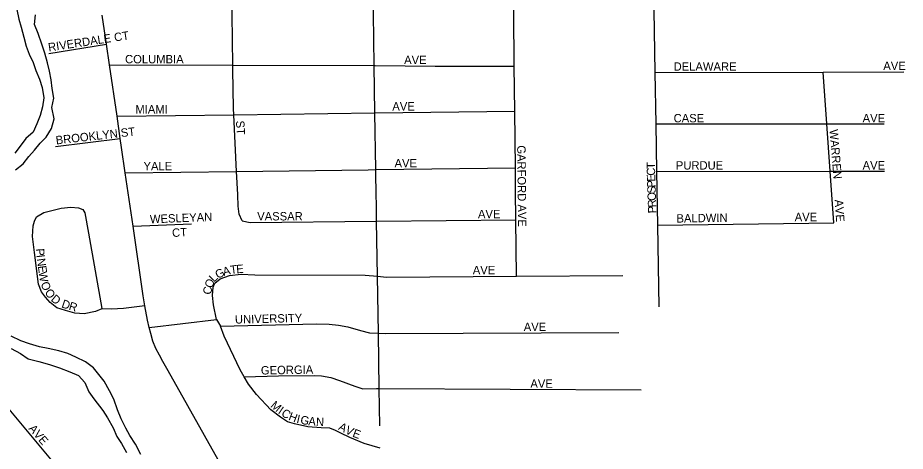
# Model space of a CAD drawing. Extents: x 1857828 to 2277390, y 930619 to 1324581.
# Drawn here: x 2077646 to 2082935, y 1221472 to 1224059 of the extents above; entities that cross this region are included whole.
import ezdxf

# ---------------------------------------------------------------- set-up
doc = ezdxf.new("R2010")
doc.units = 0
for name, color, linetype in [('GM_X_City_Street', 7, 'Continuous'), ('GM_X_City_Street_Text', 7, 'Continuous'), ('GM_X_Major_River', 7, 'Continuous')]:
    doc.layers.add(name, color=color, linetype=linetype)

msp = doc.modelspace()

# ---------------------------------------------------------------- linework, layer by layer
at = {"layer": 'GM_X_City_Street'}
for points in [[(2079782.7, 1222985.2), (2079780.2, 1223153), (2079775, 1223490.8), (2079770.7, 1223773.6), (2079765.9, 1224084.8), (2079761.3, 1224391.1), (2079756.6, 1224694.9), (2079751.2, 1225048), (2079745.7, 1225408.2), (2079740.6, 1225747.7), (2079735.5, 1226074.6), (2079730.8, 1226385.8), (2079726.5, 1226666.8), (2079721.1, 1227020.2)], [(2080613.1, 1223041.7), (2080611.7, 1223164.2), (2080608, 1223501.1), (2080605.1, 1223769.8), (2080601.6, 1224090.5), (2080598.3, 1224399.4), (2080594.9, 1224706.3), (2080591, 1225061.2), (2080587.1, 1225424.1), (2080583.5, 1225757), (2080580, 1226078.3), (2080576.5, 1226394.5), (2080573.5, 1226674.3), (2080570, 1226994.3)], [(2081468.2, 1222334), (2081460.3, 1222821.1), (2081455.1, 1223142), (2081450.5, 1223426.8), (2081445.5, 1223731.6), (2081439.4, 1224104.6), (2081434.5, 1224409.2), (2081429.3, 1224730.2), (2081423.8, 1225071.1), (2081418.2, 1225412), (2081412.5, 1225767), (2081407.3, 1226084), (2081402.1, 1226402.9), (2081397.6, 1226681.5), (2081397.4, 1226692.4)], [(2078928.2, 1223749.3), (2078928.1, 1223751.5), (2078927.8, 1223776.3), (2078923.7, 1224079.1), (2078919.5, 1224382.8), (2078915.5, 1224683.5), (2078915.1, 1224709.9)], [(2078009.5, 1221179), (2078009.1, 1221179.8), (2077998, 1221198.3), (2077931.3, 1221300.2), (2077896.6, 1221356.3), (2077842.5, 1221426.1), (2077284.2, 1222092.8), (2077253.9, 1222126.7), (2077239.8, 1222144.7), (2077229.8, 1222158.7), (2077219.6, 1222186.7), (2077213.2, 1222252.9), (2077202.8, 1222517.1), (2077194.6, 1222724.3), (2077192.6, 1222781), (2077192.3, 1222788.5), (2077197.8, 1222882.9), (2077199.4, 1223069.7), (2077201.8, 1223354.4), (2077204.6, 1223695.4), (2077205.8, 1223837.7), (2077206.6, 1223930), (2077208.3, 1224140.5)], [(2078886.5, 1221340.6), (2078876.9, 1221357.6), (2078542.6, 1221952.2), (2078510.2, 1222008.2), (2078490, 1222046.1), (2078469.8, 1222086.2), (2078451.5, 1222130.2), (2078439.2, 1222174.3), (2078429.8, 1222211.3), (2078418.8, 1222254.4), (2078404.2, 1222340.3), (2078393.9, 1222400.7), (2078333.6, 1222814.5), (2078287.1, 1223132.9), (2078265, 1223284.9), (2078257.1, 1223338.6), (2078237.5, 1223471.8), (2078192.3, 1223778.7), (2078174.2, 1223901.7), (2078148.9, 1224073.8)], [(2077830.5, 1223844.9), (2078174.2, 1223901.7)], [(2078192.3, 1223778.7), (2078927.8, 1223776.3), (2079770.7, 1223773.6), (2079775.1, 1223773.6), (2080133.3, 1223769.9), (2080605.1, 1223769.8)], [(2078956.8, 1223002.8), (2078956.7, 1223004.6), (2078949.9, 1223141.8), (2078933.1, 1223480.4), (2078931.3, 1223516.9), (2078928.2, 1223749.3)], [(2081445.5, 1223731.6), (2082446.2, 1223735.1), (2082926.5, 1223736.8)], [(2082509.5, 1222834.4), (2082487.8, 1223143.4), (2082467.9, 1223426.6), (2082446.2, 1223735.1)], [(2078237.5, 1223471.8), (2078933.1, 1223480.4), (2079775, 1223490.8), (2080608, 1223501.1)], [(2081450.5, 1223426.8), (2082467.9, 1223426.6), (2082808.8, 1223426.6)], [(2077871.5, 1223291.2), (2078257.1, 1223338.6)], [(2078287.1, 1223132.9), (2078949.9, 1223141.8), (2079733.5, 1223152.3), (2079733.5, 1223152.3)], [(2079733.5, 1223152.3), (2079780.2, 1223153), (2080611.7, 1223164.2)], [(2081455.1, 1223142), (2082487.8, 1223143.4), (2082811.3, 1223143.8)], [(2080618.8, 1222517.2), (2080615.1, 1222853.3), (2080613.2, 1223026), (2080613.1, 1223041.7)], [(2078983.7, 1222846.9), (2078965.9, 1222887.1), (2078960.1, 1222935.2), (2078956.8, 1223002.8)], [(2079803.5, 1221623.9), (2079800.1, 1221846.5), (2079795.1, 1222177.2), (2079789.9, 1222516.6), (2079784.8, 1222845.1), (2079783.1, 1222960.1), (2079782.7, 1222985.2)], [(2078404.2, 1222340.3), (2078276.5, 1222324.8), (2078240.5, 1222323), (2078204.4, 1222321.2), (2078146.4, 1222321.4), (2078110.3, 1222305.6), (2078042.2, 1222291.8), (2077986.2, 1222296.1), (2077930.3, 1222312.4), (2077878.3, 1222328.7), (2077838.5, 1222361), (2077810.6, 1222391.2), (2077786.8, 1222423.4), (2077769, 1222469.6), (2077746, 1222658.2), (2077734.6, 1222754.5), (2077736.9, 1222816.6), (2077745.1, 1222844.7), (2077757.2, 1222870.7), (2077801.4, 1222896.5), (2077905.6, 1222922.1), (2077961.6, 1222927.9), (2078007.6, 1222925.6), (2078033.6, 1222915.5), (2078045.5, 1222895.4), (2078066.8, 1222773), (2078146.4, 1222323.4)], [(2078333.6, 1222814.5), (2078681.4, 1222830.3)], [(2078983.7, 1222846.9), (2079031.9, 1222837.8), (2079784.8, 1222845.1), (2080615.1, 1222853.3)], [(2081460.3, 1222821.1), (2082509.5, 1222834.4)], [(2078830.4, 1222258.1), (2078812.9, 1222346.4), (2078807.2, 1222402.6), (2078811.5, 1222450.7), (2078819.6, 1222474.7), (2078851.7, 1222500.6), (2078907.9, 1222520.4), (2078978, 1222528.1), (2079058, 1222525.7), (2079716.3, 1222522.7), (2079789.9, 1222516.6), (2079844.3, 1222512), (2080618.8, 1222517.2), (2081251.1, 1222521.5)], [(2078429.8, 1222211.3), (2078830.4, 1222258.1), (2078854.2, 1222217.9), (2079426.6, 1222233.3), (2079502.6, 1222230.9), (2079556.6, 1222224.6), (2079612.6, 1222214.3), (2079688.5, 1222193.9), (2079742.5, 1222179.6), (2079795.1, 1222177.2), (2079838.5, 1222175.2), (2081229.2, 1222180.7)], [(2079806.8, 1221491.6), (2079710.9, 1221518.1), (2079625, 1221554.6), (2079571.1, 1221580.9), (2079539.2, 1221597.1), (2079505.3, 1221609.3), (2079455.2, 1221611.5), (2079375.2, 1221617.9), (2079295.3, 1221636.3), (2079253.3, 1221648.5), (2079211.5, 1221676.8), (2079153.7, 1221719.2), (2079068.1, 1221811.8), (2079020.4, 1221872.2), (2078995.1, 1221916.4), (2078970.9, 1221958.6), (2078875.9, 1222159.6), (2078854.2, 1222217.9)], [(2078995.1, 1221916.4), (2079200.8, 1221921.5), (2079412.9, 1221924.5), (2079456.9, 1221922.3), (2079510.9, 1221912), (2079562.8, 1221893.7), (2079654.7, 1221861.2), (2079702.6, 1221844.9), (2079784.7, 1221846.6), (2079800.1, 1221846.5), (2081361.5, 1221839.2)]]:
    msp.add_lwpolyline(points, dxfattribs=at)
at = {"layer": 'GM_X_Major_River'}
for points in [[(2077641.4, 1224108.8), (2077651.7, 1224050.6), (2077665.9, 1224002.4), (2077682.2, 1223942.3), (2077696.5, 1223890.1), (2077714.7, 1223842), (2077737, 1223791.9), (2077753.3, 1223743.8), (2077775.5, 1223691.7), (2077791.8, 1223643.6), (2077802.1, 1223581.4), (2077794.3, 1223527.1), (2077780.5, 1223474.9), (2077760.6, 1223426.6), (2077738.8, 1223376.3), (2077694.8, 1223337.9), (2077660.9, 1223293.6), (2077629, 1223251.2)], [(2077633.5, 1223150.8), (2077677.4, 1223187.2), (2077711.3, 1223231.6), (2077745.3, 1223269.9), (2077779.2, 1223310.2), (2077815.1, 1223346.5), (2077846.9, 1223398.9), (2077862.7, 1223455.2), (2077848.4, 1223523.4), (2077860.2, 1223579.7), (2077852, 1223635.9), (2077845.7, 1223688.1), (2077835.5, 1223740.2), (2077823.2, 1223790.4), (2077806.9, 1223848.5), (2077788.7, 1223900.6), (2077768.4, 1223964.8), (2077746.1, 1224018.9), (2077751.8, 1224077.2)], [(2078241, 1221720), (2078218.7, 1221784.2), (2078192.4, 1221832.2), (2078160.1, 1221890.3), (2078129.9, 1221930.3), (2078097.6, 1221970.3), (2078049.3, 1222006.2), (2077993.1, 1222034.1), (2077944.9, 1222055.9), (2077890.7, 1222071.7), (2077826.5, 1222085.5), (2077776.3, 1222095.3), (2077716.1, 1222113.1), (2077663.9, 1222130.9), (2077607.6, 1222158.7)], [(2077605.9, 1222086.4), (2077662.2, 1222056.6), (2077708.4, 1222024.7), (2077770.7, 1222008.9), (2077834.9, 1221989.1), (2077895.1, 1221969.3), (2077955.4, 1221945.5), (2078007.6, 1221923.7), (2078045.9, 1221881.7)], [(2078045.9, 1221881.7), (2078070.2, 1221827.6), (2078100.4, 1221785.6), (2078152.8, 1221715.6), (2078181.1, 1221671.5), (2078215.4, 1221611.4), (2078235.7, 1221561.3), (2078263.9, 1221519.3), (2078294.2, 1221465.2)], [(2078380.5, 1221453.6), (2078348.1, 1221515.7), (2078313.8, 1221565.7), (2078289.6, 1221609.8), (2078263.3, 1221665.9), (2078241, 1221720)]]:
    msp.add_lwpolyline(points, dxfattribs=at)

# ---------------------------------------------------------------- texts
at = {"layer": 'GM_X_City_Street_Text'}
for s, rotation, p in [('RIVERDALE CT', 8.6154, (2077830.9, 1223857.2)), ('COLUMBIA', 0, (2078285.5, 1223787)), ('AVE', 0, (2079948.7, 1223782.6)), ('DELAWARE', 0, (2081554.7, 1223742.9)), ('AVE', 0, (2082804.3, 1223747.3)), ('AVE', 0, (2079878.3, 1223505.4)), ('MIAMI', 0, (2078347.1, 1223487.7)), ('CASE', 0, (2081554.7, 1223434.9)), ('AVE', 0, (2082681.1, 1223434.9)), ('BROOKLYN ST', 6.4707, (2077875.2, 1223302.9)), ('ST', 273.5746, (2078946.1, 1223443.7)), ('WARREN', 274.7643, (2082483.6, 1223391.1)), ('GARFORD AVE', 270.5848, (2080622.5, 1223297.8)), ('YALE', 0, (2078395.5, 1223148.9)), ('AVE', 0, (2079891.5, 1223166.5)), ('T', 90.1639, (2081444.2, 1223156.2)), ('PURDUE', 0, (2081567.9, 1223153.3)), ('AVE', 0, (2082681.1, 1223153.4)), ('C', 91.2876, (2081445.1, 1223116.9)), ('E', 91.9947, (2081446.3, 1223081.9)), ('P', 92.0022, (2081447.5, 1223046.7)), ('S', 91.9947, (2081448.7, 1223011.5)), ('O', 92.0111, (2081450.3, 1222967.6)), ('R', 92.0005, (2081451.7, 1222928)), ('AVE', 273.9431, (2082514.5, 1222973)), ('P', 91.9947, (2081452.9, 1222892.8)), ('WESLEYAN', 2.2593, (2078434.7, 1222832.1)), ('VASSAR', 0, (2079073.1, 1222849.7)), ('AVE', 0, (2080388.7, 1222862.9)), ('BALDWIN', 0.8676, (2081572.2, 1222836.6)), ('AVE', 0, (2082276.3, 1222845.3)), ('CT', 3.1778, (2078566.9, 1222750.7)), ('P', 273.9104, (2077753.7, 1222681)), ('I', 277.4728, (2077756.5, 1222642.5)), ('N', 278.1486, (2077759.4, 1222620.1)), ('E', 278.2632, (2077765.7, 1222576.4)), ('W', 278.268, (2077770.7, 1222541.6)), ('G', 25.3431, (2078837, 1222500.6)), ('A', 14.3543, (2078874.4, 1222518.6)), ('T', 7.7283, (2078915.6, 1222529.2)), ('E', 4.7591, (2078949.8, 1222533.8)), ('AVE', 0, (2080357.9, 1222528.6)), ('O', 68.4462, (2078803, 1222441.5)), ('L', 45.8309, (2078816.4, 1222478.1)), ('O', 290.1159, (2077781.7, 1222474)), ('C', 84.0139, (2078799.7, 1222405.6)), ('O', 305.5341, (2077803.7, 1222419.8)), ('D', 321.3124, (2077839.6, 1222373.1)), ('D', 341.6789, (2077903.3, 1222331.9)), ('R', 343.4153, (2077946.6, 1222317.6)), ('UNIVERSITY', 1.3796, (2078940.9, 1222233.8)), ('AVE', 0, (2080661.5, 1222189.8)), ('GEORGIA', 0.9255, (2079095.3, 1221930.2)), ('AVE', 0, (2080701.1, 1221850.9)), ('M', 319.1498, (2079148.6, 1221739.5)), ('I', 325.8387, (2079193.5, 1221701.1)), ('C', 326.1188, (2079212, 1221688.6)), ('H', 339.1291, (2079255.9, 1221660.9)), ('I', 347.4956, (2079304.6, 1221642.9)), ('G', 348.4614, (2079327, 1221637.9)), ('A', 354.6881, (2079376, 1221628.3)), ('N', 357.8085, (2079422.7, 1221624)), ('AVE', 310.8125, (2077707.4, 1221605.7)), ('A', 332.2618, (2079552.7, 1221603.4)), ('V', 333.9788, (2079593.1, 1221582.2)), ('E', 339.1847, (2079637.2, 1221560.9))]:
    msp.add_text(s, height=50, rotation=rotation, dxfattribs=at).set_placement(p)

doc.saveas('drawing.dxf')
